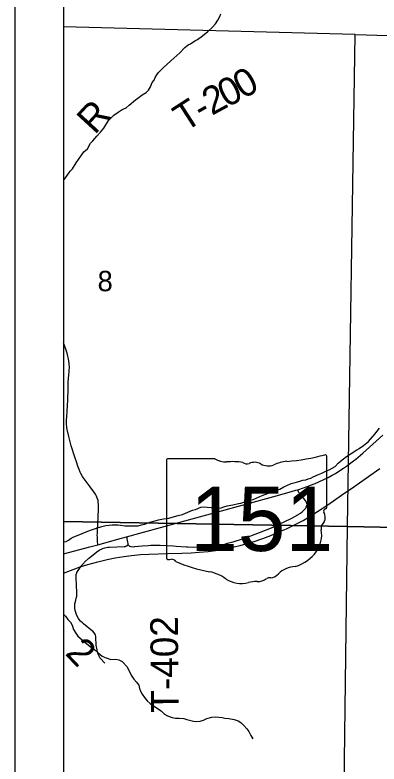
# Model space of a CAD drawing. Extents: x 0 to 34, y 0 to 22.
# Drawn here: x 2 to 2.749, y 15.391 to 16.93 of the extents above; entities that cross this region are included whole.
import ezdxf

# ---------------------------------------------------------------- set-up
doc = ezdxf.new("R2010")
doc.units = 0
for name, color, linetype in [('GM_X_County_Road', 7, 'Continuous'), ('GM_X_County_Road_Text', 7, 'Continuous'), ('GM_X_Interchange_Ramps', 7, 'Continuous'), ('GM_X_Interstate_Route', 7, 'Continuous'), ('GM_X_Minor_Lake', 7, 'Continuous'), ('GM_X_Section', 7, 'Continuous'), ('GM_X_Township_Road_Text', 7, 'Continuous'), ('GM_X_Township_Text', 7, 'Continuous'), ('GM_X_Unincorporated_Text', 7, 'Continuous'), ('SH_Cut_Line', 7, 'Continuous'), ('SH_Data', 7, 'Continuous')]:
    doc.layers.add(name, color=color, linetype=linetype)

msp = doc.modelspace()

# ---------------------------------------------------------------- linework, layer by layer
at = {"layer": 'GM_X_County_Road'}
msp.add_lwpolyline([(2.1, 15.7834), (2.1145, 15.7891), (2.1339, 15.7962), (2.15, 15.8013), (2.1701, 15.8068), (2.1897, 15.8115), (2.2062, 15.8149), (2.2238, 15.8176), (2.2396, 15.8199), (2.2578, 15.8216), (2.2752, 15.8228), (2.3142, 15.8237), (2.3428, 15.8244), (2.362, 15.8251), (2.379, 15.8263), (2.3971, 15.8282), (2.4125, 15.8303), (2.4241, 15.8322), (2.4375, 15.8348), (2.45, 15.8375), (2.4629, 15.8406), (2.4765, 15.8442), (2.4917, 15.8487), (2.5099, 15.8549), (2.5264, 15.8612), (2.5415, 15.8674), (2.5581, 15.8747), (2.5762, 15.8833), (2.5925, 15.8918), (2.6072, 15.9007), (2.6221, 15.91), (2.6436, 15.924), (2.6717, 15.9435), (2.6967, 15.9609), (2.7505, 15.9985)], dxfattribs=at)
at = {"layer": 'GM_X_Interchange_Ramps'}
for points in [[(2.1, 17.9098), (2.1, 14.1), (6.5113, 14.1), (6.5389, 15.3228), (6.5411, 15.4243), (6.5572, 16.1864), (6.5647, 16.5359), (6.5883, 17.471), (6.5943, 17.9356)], [(2.1, 15.823), (2.1539, 15.8373), (2.1706, 15.8417), (2.2114, 15.8531), (2.2293, 15.8579), (2.2994, 15.8774), (2.482, 15.927), (2.5326, 15.9411), (2.5684, 15.9511), (2.5777, 15.9537), (2.5818, 15.9548), (2.5933, 15.9587), (2.6007, 15.9614), (2.608, 15.9642), (2.6171, 15.9678), (2.6249, 15.9712), (2.6349, 15.9757), (2.644, 15.9803), (2.6521, 15.9847), (2.6588, 15.9885), (2.6679, 15.9943), (2.6755, 15.9991), (2.6815, 16.0033), (2.6935, 16.012), (2.7008, 16.0175), (2.7153, 16.0302), (2.7224, 16.0363), (2.7563, 16.0669)]]:
    msp.add_lwpolyline(points, dxfattribs=at)
at = {"layer": 'GM_X_Interstate_Route'}
for points in [[(2.1706, 15.8417), (2.1703, 15.8437), (2.1699, 15.8481), (2.1696, 15.8514), (2.1694, 15.8538), (2.1694, 15.8576), (2.1693, 15.8614), (2.1694, 15.866), (2.1695, 15.8705), (2.1702, 15.886), (2.1708, 15.8964), (2.1713, 15.9039), (2.1715, 15.9099), (2.1718, 15.9159), (2.1716, 15.9249), (2.1713, 15.9295), (2.1708, 15.9328), (2.1698, 15.9365), (2.1685, 15.9397), (2.167, 15.9428), (2.1653, 15.9459), (2.1623, 15.9505), (2.1545, 15.9608), (2.1403, 15.9803), (2.139, 15.9822), (2.1356, 15.988), (2.1342, 15.9908), (2.1317, 15.9967), (2.1292, 16.0031), (2.1262, 16.012), (2.1231, 16.0218), (2.1159, 16.0452), (2.1129, 16.056), (2.1107, 16.0643), (2.1075, 16.0784), (2.1068, 16.0824), (2.1064, 16.0854), (2.1062, 16.0882), (2.1063, 16.097), (2.1068, 16.106), (2.1073, 16.1156), (2.1079, 16.1285), (2.1084, 16.1384), (2.1088, 16.145), (2.1091, 16.1566), (2.1093, 16.1661), (2.1094, 16.1758), (2.1098, 16.1837), (2.1105, 16.1908), (2.1113, 16.1963), (2.1117, 16.2008), (2.112, 16.2061), (2.1117, 16.2145), (2.111, 16.2192), (2.1102, 16.2241), (2.109, 16.2294), (2.1072, 16.2353), (2.1052, 16.242), (2.1, 16.257)], [(2.2293, 15.8579), (2.2297, 15.8561), (2.2302, 15.8538), (2.2316, 15.8469), (2.2319, 15.8445), (2.2324, 15.8427), (2.2327, 15.842), (2.2333, 15.841), (2.2341, 15.8401), (2.2349, 15.8394), (2.2358, 15.8389), (2.2381, 15.8382), (2.2391, 15.8381), (2.2444, 15.8379), (2.2467, 15.838), (2.2619, 15.8394), (2.2742, 15.8404), (2.2796, 15.8407), (2.2837, 15.8408), (2.2986, 15.8409), (2.3255, 15.8398), (2.3318, 15.8393), (2.3527, 15.8376), (2.3558, 15.8374), (2.3666, 15.8372), (2.3794, 15.8374), (2.3861, 15.838), (2.3914, 15.8384), (2.3988, 15.839), (2.4052, 15.8396), (2.4101, 15.8402), (2.4167, 15.8411), (2.4218, 15.8418), (2.4269, 15.8426), (2.4313, 15.8434), (2.4372, 15.8448), (2.4453, 15.8469), (2.4484, 15.8478), (2.468, 15.8539), (2.4708, 15.8548), (2.4941, 15.8639), (2.5242, 15.8756), (2.5289, 15.8775), (2.5332, 15.8795), (2.5669, 15.8953), (2.5696, 15.8967), (2.5752, 15.8998), (2.5814, 15.9033), (2.5825, 15.9039), (2.5874, 15.907), (2.5903, 15.9092), (2.5928, 15.9116), (2.5953, 15.9142), (2.5967, 15.9155), (2.5978, 15.9171), (2.599, 15.919), (2.6, 15.9213), (2.6004, 15.923), (2.6006, 15.9246), (2.6003, 15.9266), (2.6001, 15.9277), (2.5999, 15.9285), (2.5995, 15.9295), (2.5984, 15.9315), (2.5972, 15.9329), (2.5931, 15.9377), (2.5898, 15.9413), (2.5856, 15.9466), (2.5848, 15.948), (2.584, 15.9492), (2.5833, 15.9509), (2.5818, 15.9548)], [(2.1846, 15.5987), (2.1753, 15.6087), (2.1746, 15.6096), (2.1736, 15.6113), (2.1717, 15.6155), (2.1711, 15.6172), (2.1691, 15.624), (2.1687, 15.6259), (2.1671, 15.6358), (2.1669, 15.6376), (2.1665, 15.6497), (2.1663, 15.6534), (2.1659, 15.6558), (2.1654, 15.6571), (2.1645, 15.6585), (2.1607, 15.6634), (2.1597, 15.6644), (2.1408, 15.6794), (2.1386, 15.6811), (2.1353, 15.6843), (2.1345, 15.6851), (2.1321, 15.6884), (2.1308, 15.6903), (2.1273, 15.6967), (2.1265, 15.6984), (2.125, 15.7029), (2.1241, 15.7067), (2.1231, 15.7118), (2.1229, 15.7136), (2.1232, 15.7193), (2.1233, 15.7204), (2.1253, 15.7279), (2.1267, 15.7339), (2.1271, 15.7362), (2.1274, 15.7424), (2.1263, 15.7603), (2.1257, 15.7724), (2.1256, 15.7749), (2.1258, 15.7794), (2.1261, 15.7808), (2.127, 15.784), (2.1272, 15.7848), (2.1284, 15.7868), (2.1312, 15.7907), (2.1321, 15.7918), (2.1356, 15.7974), (2.1363, 15.7984), (2.1421, 15.8049), (2.1431, 15.8062), (2.1519, 15.8142), (2.1539, 15.8158), (2.1685, 15.8273), (2.1729, 15.8305), (2.1744, 15.8314), (2.1791, 15.8338), (2.18, 15.8342), (2.1847, 15.8356), (2.1881, 15.8363), (2.1909, 15.8366), (2.1943, 15.8367), (2.2244, 15.8382), (2.2264, 15.8384), (2.2278, 15.8388), (2.2294, 15.8396), (2.2327, 15.842)]]:
    msp.add_lwpolyline(points, dxfattribs=at)
at = {"layer": 'GM_X_Minor_Lake'}
for points in [[(3.703, 16.8594), (3.6897, 15.9465), (3.688, 15.8589), (2.684, 15.8792), (2.6993, 16.8906)], [(2.684, 15.8792), (3.688, 15.8589), (3.6743, 14.926), (3.6733, 14.8581), (2.6707, 14.8651)]]:
    msp.add_lwpolyline(points, close=True, dxfattribs=at)
at = {"layer": 'GM_X_Township_Road_Text'}
for points in [[(2.1, 16.5908), (2.1028, 16.5941), (2.1132, 16.6095), (2.118, 16.6146), (2.1258, 16.6265), (2.1354, 16.6403), (2.1418, 16.6492), (2.1489, 16.6554), (2.1551, 16.6669), (2.16, 16.6719), (2.1682, 16.6812), (2.1756, 16.69), (2.1827, 16.6982), (2.1923, 16.7139), (2.2035, 16.7244), (2.2125, 16.731), (2.2204, 16.736), (2.2287, 16.7396), (2.2346, 16.7454), (2.2477, 16.7559), (2.2526, 16.7594), (2.2616, 16.7667), (2.2698, 16.7714), (2.2747, 16.7757), (2.2784, 16.7826), (2.282, 16.7918), (2.2861, 16.7968), (2.2883, 16.8022), (2.2917, 16.8072), (2.2954, 16.8126), (2.3047, 16.8218), (2.3204, 16.8362), (2.3387, 16.8528), (2.3492, 16.8633), (2.3563, 16.8691), (2.3612, 16.8714), (2.3702, 16.8773), (2.3754, 16.88), (2.3859, 16.8874), (2.3968, 16.8964), (2.4054, 16.9045), (2.4121, 16.9126), (2.4169, 16.9199), (2.4213, 16.9272), (2.4235, 16.9329)], [(2.1, 15.8478), (2.105, 15.8485), (2.1098, 15.8512), (2.1158, 15.8551), (2.1211, 15.8579), (2.1332, 15.8626), (2.1433, 15.867), (2.155, 15.8717), (2.1674, 15.8761), (2.1783, 15.8793), (2.187, 15.8817), (2.1938, 15.8822), (2.1999, 15.8831), (2.2124, 15.8825), (2.2173, 15.8822), (2.2257, 15.8808), (2.2374, 15.8806), (2.2533, 15.8809), (2.2605, 15.8825), (2.2669, 15.8845), (2.2774, 15.8885), (2.2857, 15.8901), (2.2951, 15.8929), (2.3053, 15.8954), (2.3163, 15.8967), (2.3284, 15.8999), (2.3355, 15.9019), (2.3446, 15.904), (2.3506, 15.9067), (2.3653, 15.9126), (2.3713, 15.9143), (2.3822, 15.919), (2.3883, 15.9195), (2.3951, 15.9188), (2.4038, 15.9182), (2.411, 15.9175), (2.4186, 15.9173), (2.4239, 15.9177), (2.4295, 15.9197), (2.4367, 15.9217), (2.448, 15.9238), (2.4594, 15.9263), (2.4643, 15.9271), (2.4707, 15.9291), (2.4839, 15.9335), (2.4895, 15.9347), (2.5019, 15.9402), (2.5083, 15.943), (2.5211, 15.9482), (2.5332, 15.9533), (2.5449, 15.9561), (2.5528, 15.9608), (2.5592, 15.9636), (2.5678, 15.9675), (2.5787, 15.9707), (2.5859, 15.9727), (2.5919, 15.9744), (2.5984, 15.9756), (2.6032, 15.9776), (2.6081, 15.9788), (2.6134, 15.9815), (2.6243, 15.9863), (2.6311, 15.9887), (2.639, 15.993), (2.6461, 15.9961), (2.6582, 16.0028), (2.6645, 16.0097), (2.6727, 16.0163), (2.6821, 16.0229), (2.6911, 16.0292), (2.7031, 16.037), (2.708, 16.0397), (2.717, 16.0456), (2.7267, 16.0537), (2.7312, 16.0587), (2.7397, 16.0691), (2.7494, 16.0811)], [(2.1, 15.6994), (2.1042, 15.6951), (2.1088, 15.6883), (2.1142, 15.6827), (2.1173, 15.6767), (2.1205, 15.6679), (2.1251, 15.6604), (2.1294, 15.654), (2.1382, 15.6465), (2.144, 15.6417), (2.1512, 15.6353), (2.1577, 15.6305), (2.1639, 15.626), (2.1708, 15.62), (2.1792, 15.6129), (2.1853, 15.6099), (2.1918, 15.6078), (2.1967, 15.6063), (2.2077, 15.6065), (2.2138, 15.6051), (2.2206, 15.6017), (2.2306, 15.5912), (2.2388, 15.5742), (2.2446, 15.5656), (2.25, 15.5592), (2.2547, 15.5532), (2.2563, 15.5467), (2.2583, 15.5407), (2.2614, 15.5346), (2.2664, 15.5282), (2.2718, 15.5211), (2.2783, 15.5158), (2.289, 15.508), (2.3005, 15.5006), (2.3078, 15.4938), (2.3135, 15.4901), (2.3234, 15.4868), (2.3299, 15.4858), (2.3378, 15.4855), (2.3473, 15.4849), (2.3534, 15.4827), (2.3614, 15.4806), (2.3674, 15.4795), (2.3724, 15.4788), (2.3807, 15.4794), (2.3875, 15.4814), (2.3946, 15.4845), (2.4048, 15.4877), (2.4124, 15.4882), (2.4264, 15.4869), (2.4317, 15.4858), (2.4401, 15.4845), (2.4507, 15.4827), (2.4591, 15.4798), (2.4648, 15.4765), (2.4706, 15.4705), (2.4767, 15.4633), (2.481, 15.4581), (2.4853, 15.4498), (2.489, 15.4428)]]:
    msp.add_lwpolyline(points, dxfattribs=at)
at = {"layer": 'GM_X_Unincorporated_Text'}
for p, q in [((2.6411, 15.9189), (2.6411, 16.0236)), ((2.3115, 16.0152), (2.3115, 15.815)), ((2.4113, 16.0186), (2.3147, 16.0186)), ((2.6411, 15.9189), (2.6411, 15.9189))]:
    msp.add_line(p, q, dxfattribs=at)
for points in [[(2.1, 16.906), (2.1, 15.8894), (2.684, 15.8792), (2.6993, 16.8906)], [(2.1, 15.8894), (2.1, 14.8693), (2.6707, 14.8651), (2.684, 15.8792)]]:
    msp.add_lwpolyline(points, close=True, dxfattribs=at)
for centre, major_axis, start_param, end_param in [((2.5237, 16.2914), (0.3495, 0), 4.814394, 5.042369), ((2.6374, 16.024), (0.00367, 0), 6.141152, 7.989035), ((2.3153, 16.0156), (0.00382, 0), 1.712693, 3.28349), ((2.4343, 16.0418), (0.037, 0), 4.042523, 4.731795), ((2.4465, 15.9062), (0.133, 0), 1.404758, 1.657858), ((2.4767, 16.0166), (0.0107, 0), 3.836095, 5.185415), ((2.4924, 15.9935), (0.0222, 0), 0.950623, 2.079405), ((2.5211, 16.0252), (0.0267, 0), 4.081561, 5.145723), ((2.5683, 15.9575), (0.0703, 0), 1.699011, 2.107814), ((2.6402, 15.9112), (0.00568, 0), 1.883978, 3.671073), ((2.6372, 15.9185), (0.00393, 0), 5.05454, 6.418171), ((2.6041, 15.898), (0.0341, 0), 5.934695, 6.695948), ((2.6542, 15.8751), (0.0248, 0), 2.387724, 3.262537), ((2.5433, 15.8617), (0.0874, 0), 5.101752, 6.440018), ((2.3153, 15.8146), (0.00385, 0), 3.00124, 4.508301), ((2.3159, 15.8351), (0.0294, 0), 4.665946, 4.897461), ((2.3219, 15.8035), (0.0106, 0), 0.519207, 1.627899), ((2.4557, 15.9833), (0.2524, 0), 4.195997, 4.488961), ((2.5801, 15.7589), (0.0479, 0), 1.647645, 2.488434), ((2.3805, 15.7251), (0.079, 0), 0.823519, 1.323587), ((2.5195, 15.7956), (0.0282, 0), 4.937069, 5.64225), ((2.4659, 15.8025), (0.0501, 0), 4.026481, 4.996735), ((2.4949, 15.7333), (0.0412, 0), 1.495662, 1.94098), ((2.4985, 15.7875), (0.0267, 0), 4.691044, 5.507374), ((2.5227, 15.7681), (0.00752, 0), 1.147584, 2.315152)]:
    msp.add_ellipse(centre, major_axis=major_axis, ratio=0.8, start_param=start_param, end_param=end_param, dxfattribs=at)
at = {"layer": 'SH_Cut_Line'}
msp.add_lwpolyline([(2.1, 17.9098), (2.1, 14.1), (8.9, 14.1), (8.9, 17.8921), (8.5492, 17.9006), (8.3297, 17.9059), (7.6027, 17.9156), (6.5943, 17.9356), (6.24, 17.9427), (6.0729, 17.9463), (5.6339, 17.9555), (5.3871, 17.9608), (4.994, 17.969), (4.9368, 17.9702), (4.9267, 17.9702), (4.5919, 17.9719), (4.4481, 17.9728), (4.1825, 17.9744), (3.7128, 17.9822), (3.7063, 17.8588), (3.604, 17.8577), (2.9484, 17.8857), (2.6711, 17.8975), (2.4376, 17.9025)], close=True, dxfattribs=at)
at = {"layer": 'SH_Data'}
for p, q in [((2, 21), (2, 14)), ((2.1, 20.9), (2.1, 14.1))]:
    msp.add_line(p, q, dxfattribs=at)

# ---------------------------------------------------------------- texts
at = {"layer": 'GM_X_County_Road_Text'}
msp.add_text('8', height=0.0419, rotation=0, dxfattribs=at).set_placement((2.1699, 16.3628))
at = {"layer": 'GM_X_Section'}
for s, height, rotation, p in [('0', 0.0568, 29.7488, (2.4691, 16.7567)), ('0', 0.0568, 26.8688, (2.4351, 16.7394)), ('2', 0.0568, 28.3957, (2.4047, 16.723)), ('R', 0.0568, 47.3603, (2.164, 16.6828)), ('T', 0.0568, 32.8806, (2.3498, 16.6889)), ('-', 0.0568, 29.8833, (2.3848, 16.7115)), ('T-402', 0.05682, 90.5614, (2.3368, 15.497)), ('2', 0.0568, 313.5001, (2.1013, 15.6177))]:
    msp.add_text(s, height=height, rotation=rotation, dxfattribs=at).set_placement(p)
at = {"layer": 'GM_X_Township_Text'}
for s in ['s', 'r']:
    msp.add_text(s, height=0.000189, dxfattribs=at).set_placement((2.4726, 15.9018))
msp.add_text('151', height=0.000189, rotation=0, dxfattribs=at).set_placement((2.4057, 15.888))
at = {"layer": 'GM_X_Unincorporated_Text'}
msp.add_text('151', height=0.13184, dxfattribs=at).set_placement((2.3601, 15.8291))

doc.saveas('drawing.dxf')
